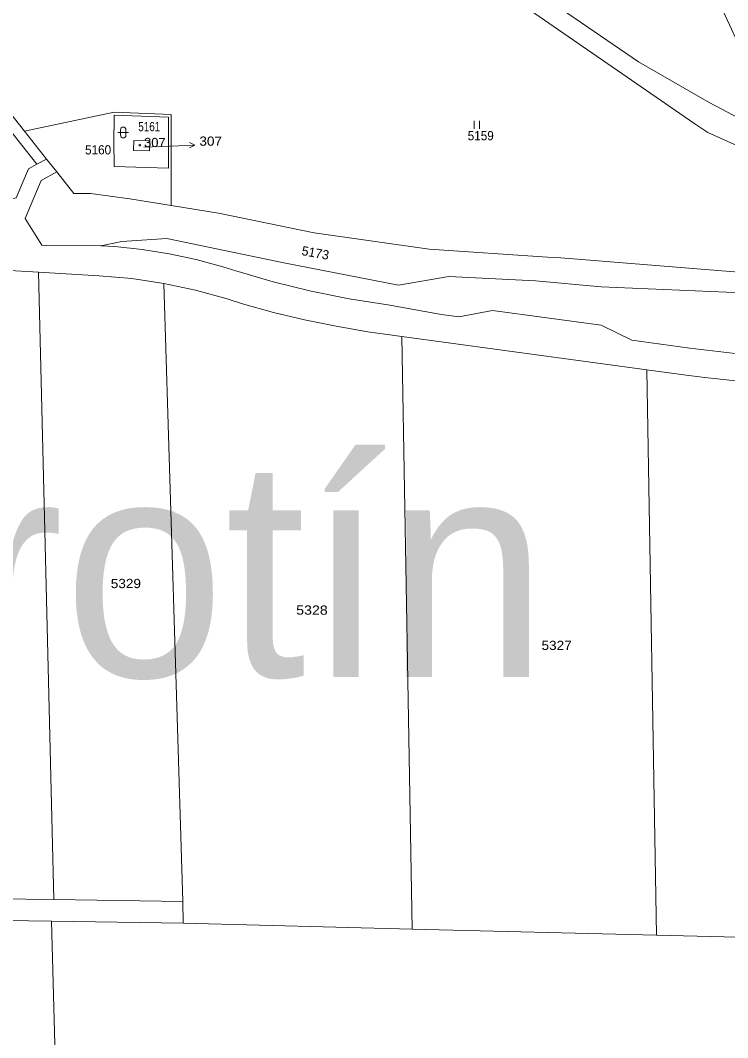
# Model space of a CAD drawing. Extents: x -590528 to -586543, y -1119609 to -1116685.
# Drawn here: x -588493.4 to -588363.1, y -1118717.9 to -1118530.4 of the extents above; entities that cross this region are included whole.
import ezdxf

# ---------------------------------------------------------------- set-up
doc = ezdxf.new("R2010")
doc.units = 0
doc.header["$LTSCALE"] = 0.68
for name, color, linetype, lineweight in [('1', 7, 'Continuous', 13), ('3', 7, 'Continuous', 13), ('6', 7, 'Continuous', 13)]:
    doc.layers.add(name, color=color, linetype=linetype, lineweight=lineweight)
doc.layers.add('5', color=7, linetype='Continuous')

msp = doc.modelspace()

# ---------------------------------------------------------------- linework, layer by layer
at = {"layer": '1'}
for p, q in [((-588354.11, -1118550.09), (-588417.94, -1118410.63)), ((-588492.66, -1118550.88), (-588543.11, -1118487.4)), ((-588544.44, -1118488.93), (-588490.36, -1118556.97)), ((-588469.6, -1118554.46), (-588469.58, -1118552.62)), ((-588490.36, -1118556.97), (-588488.58, -1118556)), ((-588472.55, -1118554.41), (-588469.6, -1118554.46)), ((-588490.36, -1118556.97), (-588491.93, -1118557.83)), ((-588456.9, -1118565.98), (-588465.65, -1118564.58)), ((-588490.11, -1118576.85), (-588528.96, -1118574.64)), ((-588490.11, -1118576.85), (-588478.88, -1118577.49)), ((-588526.08, -1118691.83), (-588487.26, -1118692.42)), ((-588463.39, -1118696.78), (-588487.68, -1118696.41))]:
    msp.add_line(p, q, dxfattribs=at)
for points in [[(-588403.05, -1118521.93), (-588379.49, -1118538.12), (-588366.48, -1118545.6), (-588361.01, -1118548.5), (-588355.05, -1118550.07), (-588354.11, -1118550.09), (-588348.89, -1118550.23), (-588342.86, -1118548.98), (-588328.2, -1118545.4), (-588227.19, -1118511.98)], [(-588226.11, -1118515.22), (-588341.38, -1118553.44), (-588344.14, -1118554.35), (-588349.91, -1118555.14), (-588355.73, -1118554.85), (-588361.39, -1118553.51), (-588366.71, -1118551.14), (-588369.11, -1118549.5), (-588401.4, -1118527.28)], [(-588465.65, -1118564.58), (-588465.63, -1118547.78), (-588476.14, -1118547.39), (-588492.66, -1118550.88), (-588488.58, -1118556), (-588486.69, -1118558.38)], [(-588469.58, -1118552.62), (-588472.51, -1118552.58), (-588472.55, -1118554.41)], [(-588491.93, -1118557.83), (-588494.2, -1118563.14), (-588497.63, -1118564.09), (-588525.61, -1118564.4)], [(-588486.69, -1118558.38), (-588489.58, -1118559.96), (-588491.44, -1118564.31), (-588492.55, -1118566.98), (-588489.48, -1118571.88), (-588488.6, -1118571.93), (-588478.57, -1118572)], [(-588486.69, -1118558.38), (-588483.55, -1118562.33), (-588480.52, -1118562.36), (-588473.24, -1118563.36), (-588465.65, -1118564.58)], [(-588393.81, -1118574.19), (-588396.27, -1118574.07), (-588418.09, -1118572.63), (-588439.26, -1118569.62), (-588456.9, -1118565.98)], [(-588466.4, -1118570.62), (-588474.75, -1118571.21), (-588478.57, -1118572), (-588476.04, -1118572.14), (-588471, -1118572.67), (-588465.99, -1118573.47), (-588461.03, -1118574.52), (-588456.14, -1118575.84)], [(-588398.49, -1118578.42), (-588414.44, -1118577.61), (-588423.75, -1118579.21), (-588444.88, -1118575.12), (-588466.4, -1118570.62)], [(-588360.39, -1118580.63), (-588361.09, -1118576.86), (-588393.81, -1118574.19)], [(-588456.14, -1118575.84), (-588453.73, -1118576.62), (-588446.83, -1118578.62), (-588439.85, -1118580.33), (-588432.8, -1118581.74), (-588425.71, -1118582.86), (-588415.83, -1118584.61), (-588412.59, -1118585.05), (-588406.38, -1118583.88), (-588386.4, -1118586.6)], [(-588466.99, -1118578.9), (-588463.51, -1118692.77), (-588487.26, -1118692.42), (-588490.11, -1118576.85)], [(-588478.88, -1118577.49), (-588472.91, -1118578.02), (-588466.99, -1118578.9)], [(-588327.07, -1118590.08), (-588344.43, -1118588.55), (-588354.17, -1118586.58), (-588360.39, -1118580.63), (-588386.39, -1118579.57), (-588398.49, -1118578.42)], [(-588455.34, -1118581.77), (-588461.12, -1118580.16), (-588466.99, -1118578.9)], [(-588377.99, -1118594.81), (-588423.09, -1118588.67), (-588429.37, -1118587.81), (-588435.22, -1118586.81), (-588441.03, -1118585.62), (-588446.8, -1118584.24), (-588452.51, -1118582.66), (-588455.34, -1118581.77)], [(-588386.4, -1118586.6), (-588380.73, -1118589.39), (-588370.01, -1118590.85), (-588361.71, -1118591.81), (-588353.38, -1118592.41), (-588345.03, -1118592.66), (-588336.67, -1118592.55)], [(-588423.09, -1118588.67), (-588421.2, -1118697.84), (-588376.17, -1118698.97)], [(-588343.05, -1118597.66), (-588346.78, -1118597.66), (-588353.63, -1118597.43), (-588360.47, -1118596.97), (-588367.29, -1118596.27), (-588370.69, -1118595.81), (-588377.99, -1118594.81)], [(-588377.99, -1118594.81), (-588376.17, -1118698.97), (-588341.27, -1118699.85), (-588343.05, -1118597.66)], [(-588463.51, -1118692.77), (-588463.39, -1118696.78), (-588421.2, -1118697.84)], [(-588483.64, -1118846.11), (-588487.68, -1118696.41), (-588534.05, -1118695.71)]]:
    msp.add_lwpolyline(points, dxfattribs=at)
msp.add_lwpolyline([(-588476.13, -1118556.67), (-588476.11, -1118557.35), (-588466.14, -1118557.7), (-588466.13, -1118548.26), (-588476.16, -1118547.89), (-588476.18, -1118553.38)], close=True, dxfattribs=at)
at = {"layer": '3'}
for p in [(-588470.65, -1118553.8), (-588461.263, -1118553.415)]:
    msp.add_line(p, (-588464.26, -1118553.54), dxfattribs=at)
msp.add_lwpolyline([(-588462.282, -1118552.958), (-588461.263, -1118553.415), (-588462.241, -1118553.957)], dxfattribs=at)
at = {"layer": '6'}
for p, q in [((-588409.81, -1118550.46), (-588409.81, -1118548.96)), ((-588408.81, -1118550.46), (-588408.81, -1118548.96)), ((-588475.47, -1118551.11), (-588473.47, -1118551.11)), ((-588474.97, -1118551.61), (-588474.97, -1118550.61)), ((-588473.97, -1118551.61), (-588473.97, -1118550.61))]:
    msp.add_line(p, q, dxfattribs=at)
msp.add_circle((-588471.4102, -1118553.4204), 0.175, dxfattribs=at)
for centre, start, end in [((-588474.47, -1118550.61), 0, 179.99999), ((-588474.47, -1118551.61), 179.99999, 359.99999)]:
    msp.add_arc(centre, 0.5, start, end, dxfattribs=at)

# ---------------------------------------------------------------- texts
at = {"layer": '3'}
for s, width, p in [('5161', 0.8, (-588471.693, -1118550.87)), ('307', 1.05, (-588470.626, -1118553.8)), ('307', 1.1, (-588460.433, -1118553.55)), ('5159', 0.95, (-588410.983, -1118552.55)), ('5160', 0.95, (-588481.503, -1118555.15)), ('5329', 1.1, (-588476.763, -1118635.04)), ('5328', 1.15, (-588442.593, -1118639.94)), ('5327', 1.1, (-588397.373, -1118646.44))]:
    msp.add_text(s, height=1.7, dxfattribs=dict(at, width=width)).set_placement(p)
msp.add_text('5173', height=1.7, rotation=349.619, dxfattribs=at).set_placement((-588441.686, -1118573.673))
at = {"layer": '5'}
msp.add_text('Borotín', height=40, dxfattribs=at).set_placement((-588568.687, -1118651.406))

doc.saveas('drawing.dxf')
